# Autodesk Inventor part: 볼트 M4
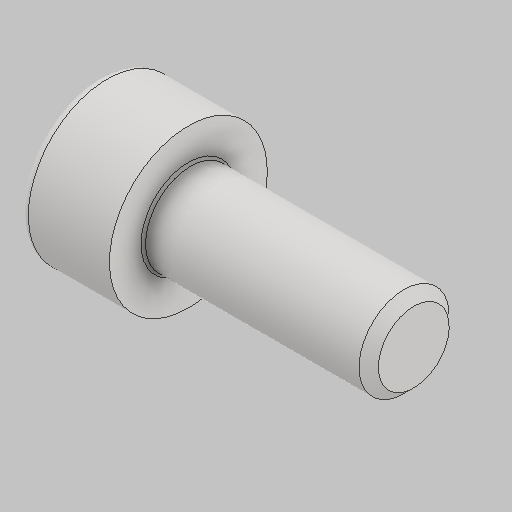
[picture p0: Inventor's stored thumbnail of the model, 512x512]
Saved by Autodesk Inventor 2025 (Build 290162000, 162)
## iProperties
Created: 2024-08
Part Number: 볼트 M4
Material: 스테인리스강
Description: 6각머리 태핑 나사
Document SubType Name: Modeling
Designer: 현기
Density: 8.08 g/cm^3
Appearance: 기본값
Author: jhkim
Sending System: Autodesk Inventor 2025
Preprocessor: ST-DEVELOPER v20
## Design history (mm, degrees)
feature "Solid1"
node "솔리드1"
